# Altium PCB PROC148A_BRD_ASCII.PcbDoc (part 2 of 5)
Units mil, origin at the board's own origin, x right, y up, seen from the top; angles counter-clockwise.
Board outline 7150 x 3764 mil, 4 copper layers (Top Layer, GND01, PWR/GND02, Bottom Layer), stack 60.96 mil thick; 312 components, 352 nets, 2206 pads, 423 vias.
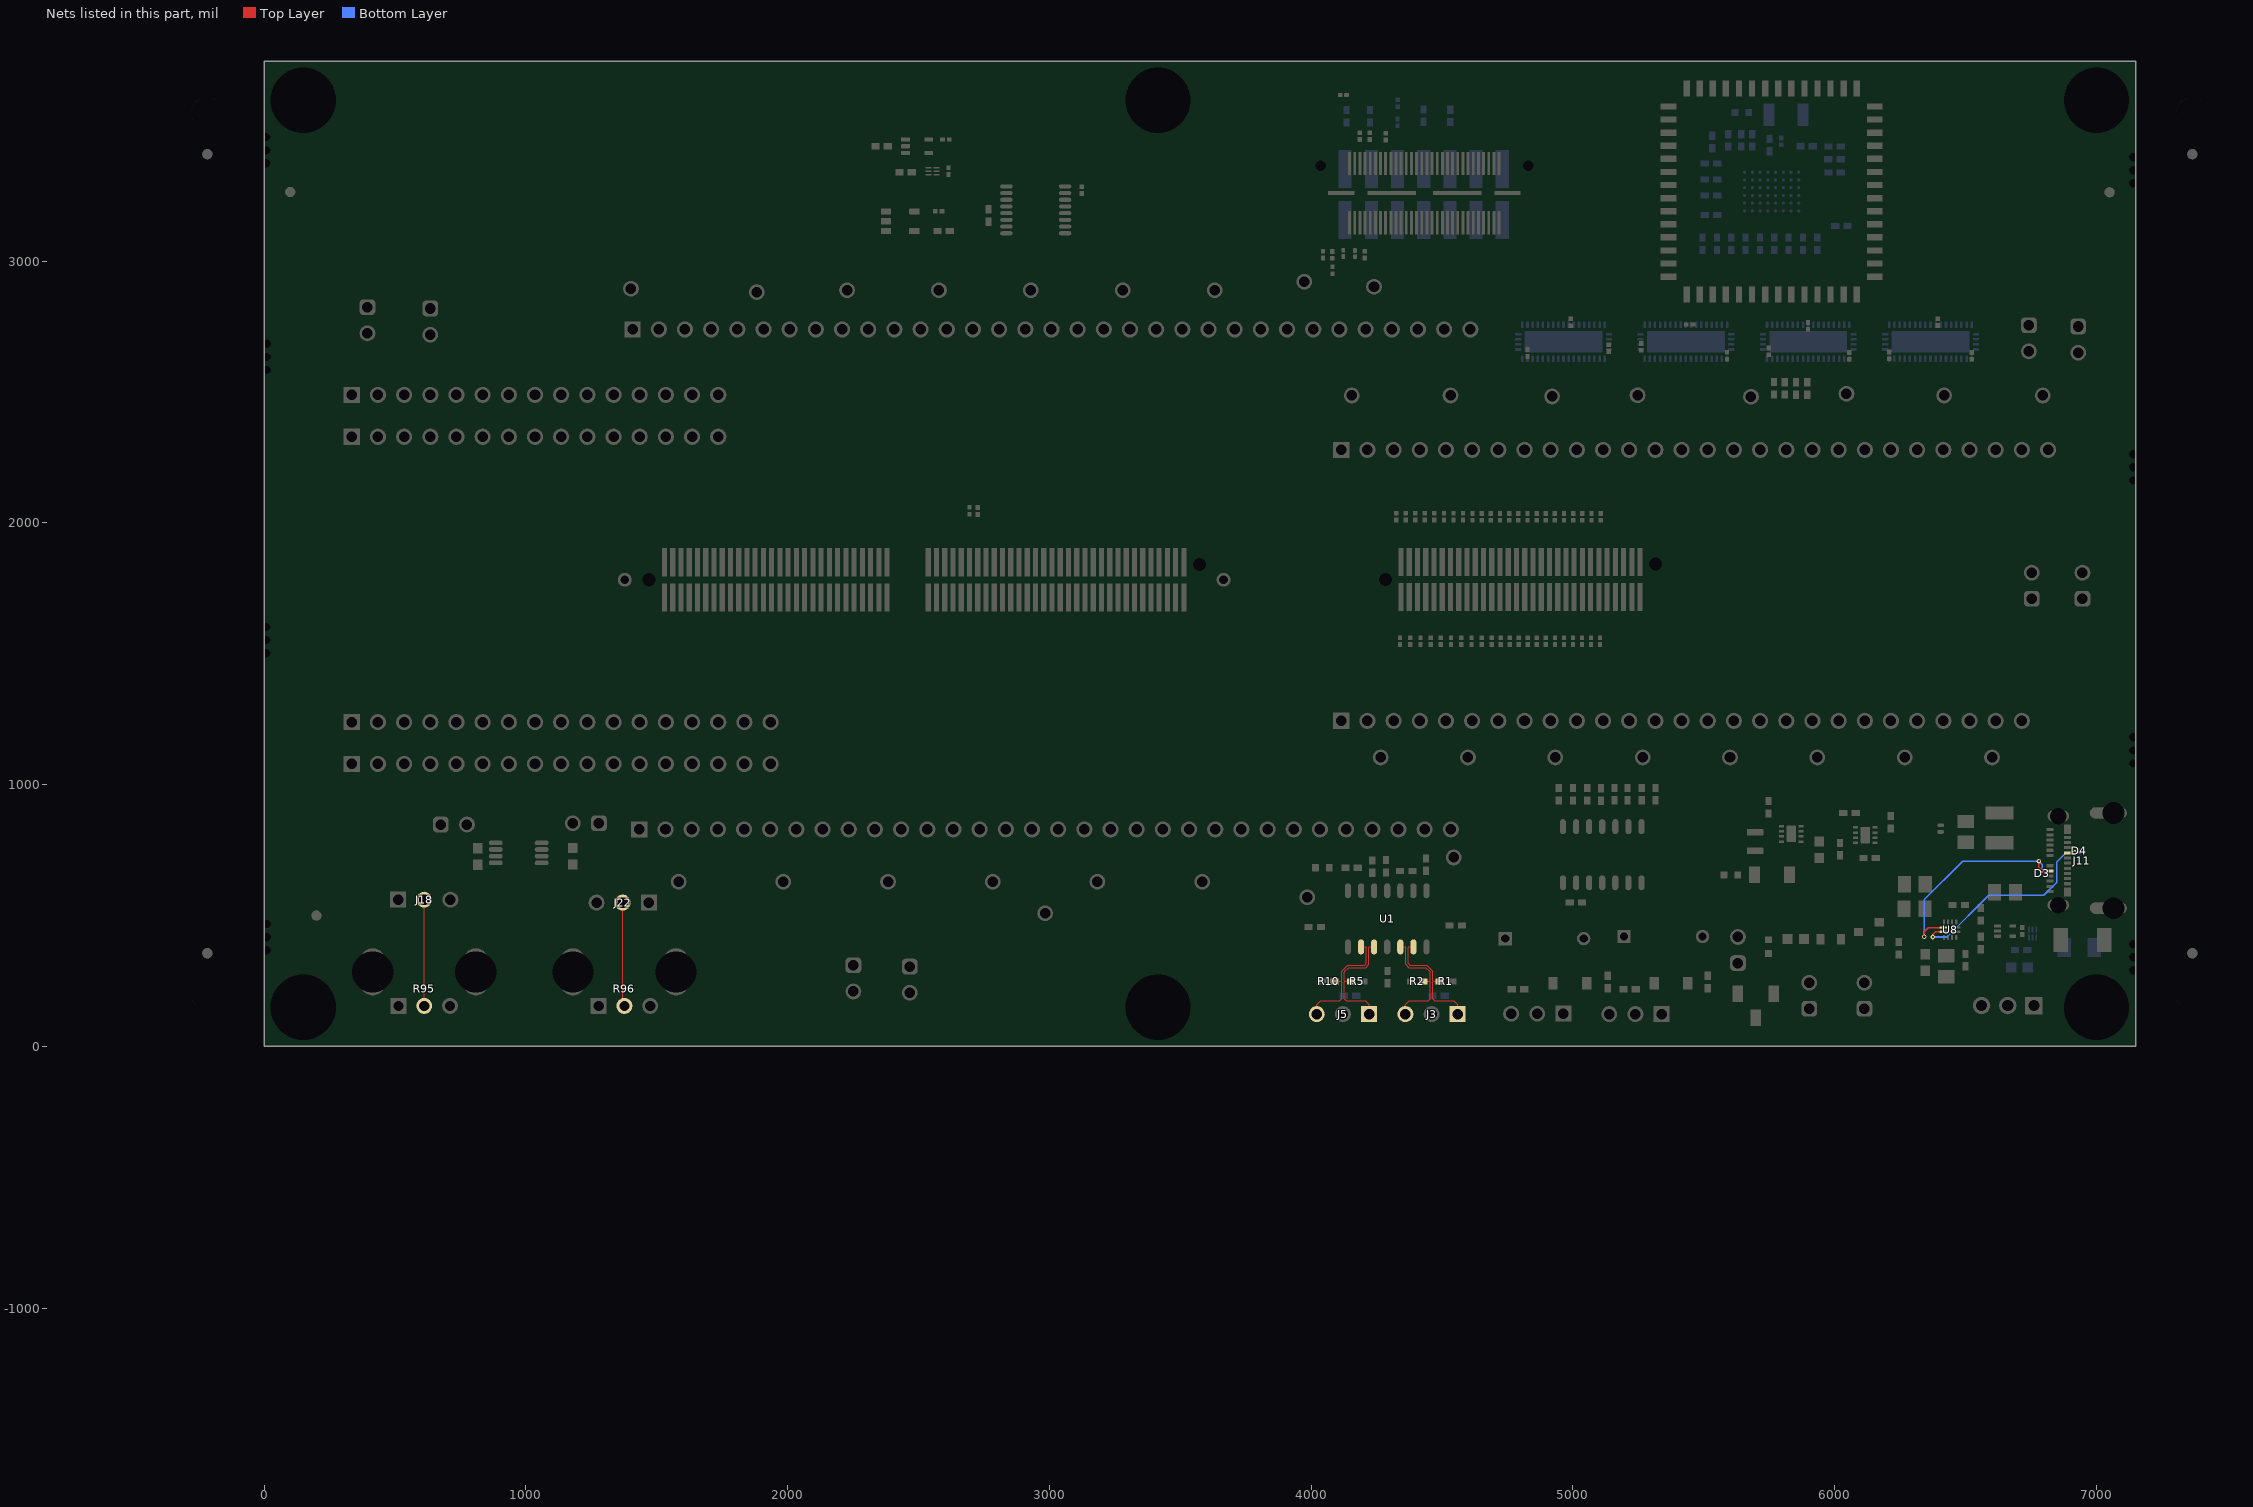
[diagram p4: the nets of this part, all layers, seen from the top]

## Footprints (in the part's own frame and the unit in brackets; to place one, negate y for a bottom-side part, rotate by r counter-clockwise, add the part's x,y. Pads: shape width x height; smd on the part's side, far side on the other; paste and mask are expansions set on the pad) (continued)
FP-2012670005_CONN_USB_9MM39_8MM21-MFG [mm]
  rrect100% 1.1x2.1 hole 1.6 slot 0.6 at 0 deg paste-1000 mask+0: 1(-4.32,3.205) 2(4.32,3.205)
  rrect100% 0.6x2.1 hole 2.1 slot 0.6 at 0 deg paste-1000 mask+0: 3(-4.62,-2.155) 4(4.62,-2.155)
  rrect100% 1.1x3.6 smd paste-1000 mask+0: 3(-4.62,-1.655) 4(4.62,-1.655)
  rrect100% 1.1x3.6 smd far side paste-1000 mask+0: 3(-4.62,-1.655) 4(4.62,-1.655)
  rrect33% 0.3x0.7 smd paste+0 mask+0: A1(-3,4.015) A2(-2.5,4.015) A3(-2,4.015) A4(-1.5,4.015) A5(-1,4.015) A6(-0.5,4.015) A7(0.5,4.015) A8(1,4.015) A9(1.5,4.015) A10(2,4.015) A11(2.5,4.015) A12(3,4.015) B2(2.25,2.315) B3(1.75,2.315) B4(1.25,2.315) B5(0.75,2.315) B6(0.25,2.315) B7(-0.25,2.315) B8(-0.75,2.315) B9(-1.25,2.315) B10(-1.75,2.315) B11(-2.25,2.315)
  rrect14% 0.9x0.7 smd paste+0 mask+0: B1(3.05,2.315) B12(-3.05,2.315)
  silkscreen extent -4.77,0.52 4.77,5.03
FP-A6TN-1104_PTH_SW_7MM50_4MM48-MFG [mm]
  rect 1.3x1.3 hole 0.8 paste-1000 mask+0: 1(0,-3.81)
  round 1.3 hole 0.8 paste-1000 mask+0: 2(0,3.81)
FP-BLM18EG121SN1D_0603-MFG [mm]
  rrect15% 0.65x0.7 smd paste+0 mask+0: 1(-0.675,0) 2(0.675,0)
  silkscreen extent -0.87,-0.8 0.87,0.8
FP-DSG0008A-MFG [mm]
  rrect40% 0.5x0.25 smd paste+0 mask+0: 1(-0.95,0.75) 2(-0.95,0.25) 3(-0.95,-0.25) 4(-0.95,-0.75) 5(0.95,-0.75) 6(0.95,-0.25) 7(0.95,0.25) 8(0.95,0.75)
  rrect11% 0.9x1.6 smd paste-1000 mask+0: 9(0,0)
  silkscreen extent -1.88,-1.39 1,1.4
FP-ERJ-1GNF33R2C_0201-IPC_B [mil]
  rrect28% 17.88x14.28 smd paste+0 mask+0: 1(-11.98,0) 2(11.98,0)
  silkscreen extent -21,-23 21,23
FP-IS67WVE4M16EBLL-70BLA1_TFBGA48-IPC_C [mm]
  round 0.298 smd paste+0 mask+0: A1(-1.875,2.625) A2(-1.125,2.625) A3(-0.375,2.625) A4(0.375,2.625) A5(1.125,2.625) A6(1.875,2.625) B1(-1.875,1.875) B2(-1.125,1.875) B3(-0.375,1.875) B4(0.375,1.875) B5(1.125,1.875) B6(1.875,1.875) C1(-1.875,1.125) C2(-1.125,1.125) C3(-0.375,1.125) C4(0.375,1.125) C5(1.125,1.125) C6(1.875,1.125) D1(-1.875,0.375) D2(-1.125,0.375) D3(-0.375,0.375) D4(0.375,0.375) D5(1.125,0.375) D6(1.875,0.375) E1(-1.875,-0.375) E2(-1.125,-0.375) E3(-0.375,-0.375) E4(0.375,-0.375) E5(1.125,-0.375) E6(1.875,-0.375) F1(-1.875,-1.125) F2(-1.125,-1.125) F3(-0.375,-1.125) F4(0.375,-1.125) F5(1.125,-1.125) F6(1.875,-1.125) G1(-1.875,-1.875) G2(-1.125,-1.875) G3(-0.375,-1.875) G4(0.375,-1.875) G5(1.125,-1.875) G6(1.875,-1.875) H1(-1.875,-2.625) H2(-1.125,-2.625) H3(-0.375,-2.625) H4(0.375,-2.625) H5(1.125,-2.625) H6(1.875,-2.625)
  silkscreen extent -3.62,-4 3,4
FP-PTV09A-8025U-B103_PTH_POT_27MM4_9MM7-MFG [mm]
  rrect6% 1.55x1.55 hole 1 paste-1000 mask+0: 1(-2.5,8)
  round 1.55 hole 1 paste-1000 mask+0: 2(0,8) 3(2.5,8)
  rrect100% 2.4x4.6 hole 4 slot 1.8 at 0 deg paste-1000 mask+0: 4(-5,11.3) 5(5,11.3)
  silkscreen extent -5.62,4.5 4.85,13.95
FP-TSW-115-23-T-S-MFG [mm]
  rect 1.57x1.57 hole 1.02 paste-1000 mask+0: 1(-17.78,0)
  round 1.57 hole 1.02 paste-1000 mask+0: 2(-15.24,0) 3(-12.7,0) 4(-10.16,0) 5(-7.62,0) 6(-5.08,0) 7(-2.54,0) 8(0,0) 9(2.54,0) 10(5.08,0) 11(7.62,0) 12(10.16,0) 13(12.7,0) 14(15.24,0) 15(17.78,0)
  silkscreen extent -19.24,-1.95 19.24,1.34
FP-TSW-117-23-T-S-MFG [mm]
  rect 1.57x1.57 hole 1.02 paste-1000 mask+0: 1(-20.32,0)
  round 1.57 hole 1.02 paste-1000 mask+0: 2(-17.78,0) 3(-15.24,0) 4(-12.7,0) 5(-10.16,0) 6(-7.62,0) 7(-5.08,0) 8(-2.54,0) 9(0,0) 10(2.54,0) 11(5.08,0) 12(7.62,0) 13(10.16,0) 14(12.7,0) 15(15.24,0) 16(17.78,0) 17(20.32,0)
  silkscreen extent -21.78,-1.95 21.78,1.34
FP-TSW-127-23-T-S-MFG [mm]
  rect 1.57x1.57 hole 1.02 paste-1000 mask+0: 1(-33.02,0)
  round 1.57 hole 1.02 paste-1000 mask+0: 2(-30.48,0) 3(-27.94,0) 4(-25.4,0) 5(-22.86,0) 6(-20.32,0) 7(-17.78,0) 8(-15.24,0) 9(-12.7,0) 10(-10.16,0) 11(-7.62,0) 12(-5.08,0) 13(-2.54,0) 14(0,0) 15(2.54,0) 16(5.08,0) 17(7.62,0) 18(10.16,0) 19(12.7,0) 20(15.24,0) 21(17.78,0) 22(20.32,0) 23(22.86,0) 24(25.4,0) 25(27.94,0) 26(30.48,0) 27(33.02,0)
  silkscreen extent -35.14,-1.34 34.48,1.34
FP-TSW-128-23-T-S-0 [mm]
  rect 1.57x1.57 hole 1.02 paste-1000 mask+0: 1(-34.29,0)
  round 1.57 hole 1.02 paste-1000 mask+0: 2(-31.75,0) 3(-29.21,0) 4(-26.67,0) 5(-24.13,0) 6(-21.59,0) 7(-19.05,0) 8(-16.51,0) 9(-13.97,0) 10(-11.43,0) 11(-8.89,0) 12(-6.35,0) 13(-3.81,0) 14(-1.27,0) 15(1.27,0) 16(3.81,0) 17(6.35,0) 18(8.89,0) 19(11.43,0) 20(13.97,0) 21(16.51,0) 22(19.05,0) 23(21.59,0) 24(24.13,0) 25(26.67,0) 26(29.21,0) 27(31.75,0) 28(34.29,0)
  silkscreen extent -35.75,-1.95 35.75,1.34
FP-TSW-132-23-T-S-MFG [mm]
  rect 1.57x1.57 hole 1.02 paste-1000 mask+0: 1(-39.37,0)
  round 1.57 hole 1.02 paste-1000 mask+0: 2(-36.83,0) 3(-34.29,0) 4(-31.75,0) 5(-29.21,0) 6(-26.67,0) 7(-24.13,0) 8(-21.59,0) 9(-19.05,0) 10(-16.51,0) 11(-13.97,0) 12(-11.43,0) 13(-8.89,0) 14(-6.35,0) 15(-3.81,0) 16(-1.27,0) 17(1.27,0) 18(3.81,0) 19(6.35,0) 20(8.89,0) 21(11.43,0) 22(13.97,0) 23(16.51,0) 24(19.05,0) 25(21.59,0) 26(24.13,0) 27(26.67,0) 28(29.21,0) 29(31.75,0) 30(34.29,0) 31(36.83,0) 32(39.37,0)
  silkscreen extent -41.55,-1.34 40.83,1.34
FP-TSW-133-23-T-S-MFG [mm]
  rect 1.57x1.57 hole 1.02 paste-1000 mask+0: 1(-40.64,0)
  round 1.57 hole 1.02 paste-1000 mask+0: 2(-38.1,0) 3(-35.56,0) 4(-33.02,0) 5(-30.48,0) 6(-27.94,0) 7(-25.4,0) 8(-22.86,0) 9(-20.32,0) 10(-17.78,0) 11(-15.24,0) 12(-12.7,0) 13(-10.16,0) 14(-7.62,0) 15(-5.08,0) 16(-2.54,0) 17(0,0) 18(2.54,0) 19(5.08,0) 20(7.62,0) 21(10.16,0) 22(12.7,0) 23(15.24,0) 24(17.78,0) 25(20.32,0) 26(22.86,0) 27(25.4,0) 28(27.94,0) 29(30.48,0) 30(33.02,0) 31(35.56,0) 32(38.1,0) 33(40.64,0)
  silkscreen extent -42.1,-1.95 42.1,1.34
LP-M67K_Green [mm] "Osram"
  rect 0.8x1 smd: 1(-1,0) 2(1,0)
  silkscreen extent -0.3,-0.75 1.78,0.75
MHNP_M3_PANHEAD_PHILLIPS#1 [mil]
  round 121 hole 126 unplated mask+0: ""(0,0)
  Keep-Out Layer circle w1: c0,0 r126
MHNP_M3_PANHEAD_PHILLIPS#2 [mil]
  round 245 hole 250 unplated mask+0: ""(0,0)
  Keep-Out Layer circle w1: c0,0 r126
Molex_0022284033 [mm] "Header, 2.54mm, 3x1, TH"
  rect 1.55x1.55 hole 1.02: 1(-2.54,0)
  round 1.55 hole 1.02: 2(0,0) 3(2.54,0)
  silkscreen extent -3.81,-1.24 3.81,1.5
MSPL_GPMC_MOD [mil]
  rect 61x24 smd mask+0: 1(-393.7,325) 2(-393.7,275) 3(-393.7,225) 4(-393.7,175) 5(-393.7,125) 6(-393.7,75) 7(-393.7,25) 8(-393.7,-25) 9(-393.7,-75) 10(-393.7,-125) 11(-393.7,-175) 12(-393.7,-225) 13(-393.7,-275) 14(-393.7,-325) 29(393.7,-325) 30(393.7,-275) 31(393.7,-225) 32(393.7,-175) 33(393.7,-125) 34(393.7,-75) 35(393.7,-25) 36(393.7,25) 37(393.7,75) 38(393.7,125) 39(393.7,175) 40(393.7,225) 41(393.7,275) 42(393.7,325)
  rect 24x61 smd mask+0: 15(-325,-393.7) 16(-275,-393.7) 17(-225,-393.7) 18(-175,-393.7) 19(-125,-393.7) 20(-75,-393.7) 21(-25,-393.7) 22(25,-393.7) 23(75,-393.7) 24(125,-393.7) 25(175,-393.7) 26(225,-393.7) 27(275,-393.7) 28(325,-393.7) 43(325,393.7) 44(275,393.7) 45(225,393.7) 46(175,393.7) 47(125,393.7) 48(75,393.7) 49(25,393.7) 50(-25,393.7) 51(-75,393.7) 52(-125,393.7) 53(-175,393.7) 54(-225,393.7) 55(-275,393.7) 56(-325,393.7)
  silkscreen extent -450,-405 405,405
ONSC-SOT-23-3-318-08_V [mm] "SOT23, 3-Leads, Body 2.92x1.3mm, Pitch 0.95mm"
  rect 0.9x0.8 smd: 1(-1,0.95) 2(-1,-0.95) 3(1,0)
  silkscreen extent -1.13,-1.46 0.65,2.02
PW0016A_L [mm] "TSOP, 16-Leads, Body 5x4.4mm, Pitch 0.65mm, IPC High Density"
  oval 1.2x0.4 smd: 1(-2.85,2.275) 2(-2.85,1.625) 3(-2.85,0.975) 4(-2.85,0.325) 5(-2.85,-0.325) 6(-2.85,-0.975) 7(-2.85,-1.625) 8(-2.85,-2.275) 9(2.85,-2.275) 10(2.85,-1.625) 11(2.85,-0.975) 12(2.85,-0.325) 13(2.85,0.325) 14(2.85,0.975) 15(2.85,1.625) 16(2.85,2.275)
  silkscreen extent -2,-2.55 1.85,2.55
RUA0042A-MFG [mm]
  rrect40% 0.6x0.25 smd paste+0 mask+0: 1(-1.65,4) 2(-1.65,3.5) 3(-1.65,3) 4(-1.65,2.5) 5(-1.65,2) 6(-1.65,1.5) 7(-1.65,1) 8(-1.65,0.5) 9(-1.65,0) 10(-1.65,-0.5) 11(-1.65,-1) 12(-1.65,-1.5) 13(-1.65,-2) 14(-1.65,-2.5) 15(-1.65,-3) 16(-1.65,-3.5) 17(-1.65,-4) 22(1.65,-4) 23(1.65,-3.5) 24(1.65,-3) 25(1.65,-2.5) 26(1.65,-2) 27(1.65,-1.5) 28(1.65,-1) 29(1.65,-0.5) 30(1.65,0) 31(1.65,0.5) 32(1.65,1) 33(1.65,1.5) 34(1.65,2) 35(1.65,2.5) 36(1.65,3) 37(1.65,3.5) 38(1.65,4)
  rrect40% 0.25x0.6 smd paste+0 mask+0: 18(-0.75,-4.4) 19(-0.25,-4.4) 20(0.25,-4.4) 21(0.75,-4.4) 39(0.75,4.4) 40(0.25,4.4) 41(-0.25,4.4) 42(-0.75,4.4)
  rrect5% 2.05x7.55 smd paste-1000 mask+0: 43(0,0)
  silkscreen extent -2.65,-4.55 1.8,4.55
RWB0012A [mm] "QFN, 12-Leads, Body 1.6x1.6mm, Pitch 0.4mm"
  rrect57% 0.7x0.2 smd paste-0.1: 1(-0.65,0.2) 2(-0.65,-0.2) 7(0.65,-0.2) 8(0.65,0.2)
  rrect57% 0.2x0.5 smd: 3(-0.6,-0.75) 4(-0.2,-0.75) 5(0.2,-0.75) 6(0.6,-0.75) 9(0.6,0.75) 10(0.2,0.75) 11(-0.2,0.75) 12(-0.6,0.75)
  silkscreen extent -0.92,-0.91 0.92,0.91
Samtec_QSH-030-01-X-D-A [mm] "Receptacle, 0.5 mm, 30x2, TH"
  rect 2.27x0.279 smd: 1(-2.865,7.25) 2(2.865,7.25) 3(-2.865,6.75) 4(2.865,6.75) 5(-2.865,6.25) 6(2.865,6.25) 7(-2.865,5.75) 8(2.865,5.75) 9(-2.865,5.25) 10(2.865,5.25) 11(-2.865,4.75) 12(2.865,4.75) 13(-2.865,4.25) 14(2.865,4.25) 15(-2.865,3.75) 16(2.865,3.75) 17(-2.865,3.25) 18(2.865,3.25) 19(-2.865,2.75) 20(2.865,2.75) 21(-2.865,2.25) 22(2.865,2.25) 23(-2.865,1.75) 24(2.865,1.75) 25(-2.865,1.25) 26(2.865,1.25) 27(-2.865,0.75) 28(2.865,0.75) 29(-2.865,0.25) 30(2.865,0.25) 31(-2.865,-0.25) 32(2.865,-0.25) 33(-2.865,-0.75) 34(2.865,-0.75) 35(-2.865,-1.25) 36(2.865,-1.25) 37(-2.865,-1.75) 38(2.865,-1.75) 39(-2.865,-2.25) 40(2.865,-2.25) 41(-2.865,-2.75) 42(2.865,-2.75) 43(-2.865,-3.25) 44(2.865,-3.25) 45(-2.865,-3.75) 46(2.865,-3.75) 47(-2.865,-4.25) 48(2.865,-4.25) 49(-2.865,-4.75) 50(2.865,-4.75) 51(-2.865,-5.25) 52(2.865,-5.25) 53(-2.865,-5.75) 54(2.865,-5.75) 55(-2.865,-6.25) 56(2.865,-6.25) 57(-2.865,-6.75) 58(2.865,-6.75) 59(-2.865,-7.25) 60(2.865,-7.25)
  round 0 hole 1.02 unplated: MH1(2.67,10.065) MH2(2.67,-10.065)
  rect 0.43x2.54 smd: MP1(0,8.065) MP4(0,-8.065)
  rect 0.43x4.7 smd: MP2(0,3.175) MP3(0,-3.175)
  silkscreen extent -3.9,-10.66 3.62,10.66
Samtec_TSM-107-01-x-DV [mm] "Header, 2.54mm, 7x2, SMT"
  rect 3.68x1.27 smd: 1(-2.475,7.62) 2(2.475,7.62) 3(-2.475,5.08) 4(2.475,5.08) 5(-2.475,2.54) 6(2.475,2.54) 7(-2.475,0) 8(2.475,0) 9(-2.475,-2.54) 10(2.475,-2.54) 11(-2.475,-5.08) 12(2.475,-5.08) 13(-2.475,-7.62) 14(2.475,-7.62)
  silkscreen extent -1.65,-8.89 1.65,9.03
Samtec_TSW-101-08-x-S [mm] "Header, 2.54mm, 1x1, TH"
  round 1.53 hole 1.02: 1(0,0)
Samtec_TSW-102-08-x-S [mm] "Header, 2.54mm, 2x1, TH"
  rrect50% 1.53x1.53 hole 1.02: 1(-1.27,0)
  round 1.53 hole 1.02: 2(1.27,0)
  silkscreen extent -2.67,-1.27 2.54,1.7
SOD-123 [mm] "On Semi recommended land pattern"
  rect 0.915x1.22 smd: 1(-1.637,0) 2(1.637,0)
  silkscreen extent -2.74,-1.17 2.03,1.17
SW_CAS-120TA [mm] "COPAL ELECTRONICS"
  rect 1.6x1 smd: 1(-1.15,1.75) 2(1.15,0) 3(-1.15,-1.75)
  silkscreen extent -2,-2.85 1.4,2.92
TFM201610ALMA [mm] "TDK"
  rrect17% 0.6x1.6 smd: 1(-0.9,0) 2(0.9,0)
TI_Stacked_Overlay_Small [mil]
WEEE_Minimum [mil] "WEEElie bin"
  silkscreen extent 22,-71 54,74
Wurth_60900213421 [mil] "Shunt, 2.54mm, Black"
  round 1 on Mech3: 0(0,0)

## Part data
C1 C2 C5: library part CMP-0006675-2, "CAP, CERM, 0.1 uF, 50 V, +/- 20%, X7R, 0402"
C3 C4: library part CMP-0006712-2, "CAP, CERM, 4700 pF, 100 V, +/- 10%, X7R, 0402"
C6 C7: library part CMP-0084239-1, "CAP, CERM, 220 pF, 50 V,+/- 10%, X8R, AEC-Q200 Grade 0, 0402"
C8 C26 C27 C29: library part CMP-0007727-2, "CAP, CERM, 0.1 uF, 50 V, +/- 20%, X7R, 0805"
C9 C11 C12 C13 C14 C15 C16 C17 C18 C19 C20 C21 C22 C23 C24 C25 C37 C38 C39 C40 C43: library part CMP-0009717-2, "CAP, CERM, 0.1 uF, 16 V, +/- 10%, X5R, 0201"
C10: library part CMP-0081135-1, "CAP, CERM, 10 µF, 50 V,+/- 10%, X7R, 1210"
C28: library part CMP-0079201-1, "CAP, CERM, 10 µF, 50 V,+/- 10%, X7R, 1210"
C30 C41: library part CMP-0007206-4, "CAP, CERM, 300 pF, 50 V, +/- 5%, C0G/NP0, 0603"
C31: library part CMP-0006412-2, "CAP, CERM, 1000 pF, 50 V, +/- 5%, C0G/NP0, 0402"
C32: library part CMP-0008959-2, "CAP, CERM, 22 uF, 10 V, +/- 10%, X7R, 1206"
C33: library part CMP-0007501-5, "CAP, CERM, 10 uF, 25 V, +/- 20%, X5R, 0603"
C34: library part CMP-0009436-2, "CAP, CERM, 1000 pF, 2000 V, +/- 10%, X7R, 1808"
C35 C36: library part CMP-0006608-2, "CAP, CERM, 1 uF, 25 V, +/- 10%, X5R, 0402"
C44: library part CMP-0007174-4, "CAP, CERM, 0.01 uF, 50 V, +/- 5%, C0G/NP0, 0603"
D1 D6: library part CMP-0029001-2, "Diode, Ultrafast, 100 V, 0.15 A, SOD-123"
D2: library part CMP-0073591-4, "Automotive 1-Channel Ultra-Low-Capacitance IEC ESD Protection Diode, DPY0002A (X1SON-2)"
D3 D4: library part CMP-0073601-1, "1-Channel ESD Protection Diode for USB Type-C and Thunderbolt 3, DPL0002A (X2SON-2)"
D5: library part CMP-0002879-2, "LED, Green, SMD"
FB3 FB4 FB5 FB6: library part CMP-0089199-1, "120 Ohms @ 100MHz 1  Ferrite Bead 0603 (1608 Metric) 2A 40mOhm"
FID1 FID2 FID3 FID4 FID5 FID6: library part CMP-0077181-1, "Fiducial mark.  There is nothing to buy or mount."
J1: library part CMP-0003859-2, "C2000 controlCARD-180HSEC (60-pin addon) connector, SMT"
J2: library part CMP-0003814-2, "C2000 controlCARD-120HSEC connector, SMT"
J3 J5 J7 J8 J18 J22: library part CMP-0055332-1, "Header, 2.54mm, 3x1, Tin, TH"
J4 J13 J16 J17 J19 J23 J26 J27 J28 J29 J30 J65 J66: library part CMP-0077643-1, "Header, 2.54mm, 2x1, Gold, TH"
J6 J14: library part CMP-02766-001472-1, "CONN HEADER VERT 17POS 2.54MM"
J9: library part CMP-0075524-1, "Receptacle, 0.5 mm, 30x2, Gold, TH"
J10: library part CMP-0075611-2, "Header, 2.54mm, 7x2, Gold, SMT"
J11: library part CMP-0093552-1, "USB-C (USB TYPE-C) USB 3.2 Gen 2 (USB 3.1 Gen 2, Superspeed + (USB 3.1)) Receptacle Connector 24 Position Surface Mount, Right Angle; Through Hole"
J12 J15: library part CMP-02766-001466-1, "CONN HEADER VERT 15POS 2.54MM"
J20: library part CMP-02766-001470-1, "CONN HEADER VERT 32POS 2.54MM"
J21: library part CMP-02766-001386-1, "CONN HEADER VERT 33POS 2.54MM"
J24: library part CMP-02766-001392-1, "CONN HEADER VERT 27POS 2.54MM"
J25: library part CMP-02766-001385-1, "CONN HEADER VERT 28POS 2.54MM"
J31 J32 J33 J34 J35 J36 J37 J38 J39 J40 J41 J42 J43 J44 J45 J46 J47 J48 J49 J50 J51 J52 J53 J54 J55 J56 J57 J58 J59 J60 J61 J62 J63 J64: library part CMP-0079328-1, "Header, 2.54mm, 1x1, Gold, TH"
L1: library part CMP-0081094-1, "Inductor, Shielded, Metal Composite, 2.2 µH, 1.9 A, 0.152 ohm, AEC-Q200 Grade 0, SMD"
Logo1: library part CMP-0074844-1
Logo2: library part CMP-0074838-1, "Texas Instrument Corporate Signature"
Logo3: library part CMP-0074847-1, "FCC_disclaimer"
Logo4: library part CMP-0074769-1
Q1: library part CMP-1058-00767-1, "Power MOSFET, 200 mA, 50 V, N-Channel, 3-Pin SOT-23, Pb-Free, Tape and Reel"
R1 R2 R5 R10: library part CMP-0026462-2, "RES, 59.0, 1%, 0.063 W, AEC-Q200 Grade 0, 0402"
R3 R6 R53 R56 R89 R92: library part CMP-0026822-3, "RES, 0, 5%, 0.063 W, AEC-Q200 Grade 0, 0402"
R4 R7 R88 R91: library part CMP-0026908-3, "RES, 33, 5%, 0.063 W, AEC-Q200 Grade 0, 0402"
R8 R9: library part CMP-0026994-4, "RES, 10 k, 5%, 0.1 W, AEC-Q200 Grade 0, 0402"
R11: library part CMP-0026829-3, "RES, 110, 5%, 0.063 W, AEC-Q200 Grade 0, 0402"
R12 R48 R59 R60 R61 R62 R63 R64 R65 R66 R67 R68 R69 R70 R71 R72: library part CMP-0026880-3, "RES, 22, 5%, 0.063 W, AEC-Q200 Grade 0, 0402"
R13 R14 R20 R22 R37 R38 R39 R73 R74 R75 R76 R77 R78 R79 R80 R81 R82 R83 R85 R86 R87 R90 R93: library part CMP-0026825-5, "RES, 10 k, 5%, 0.063 W, AEC-Q200 Grade 0, 0402"
R15 R16 R23: library part CMP-0083836-1, "RES, 100, 1%, 0.05 W, 0201"
R17: library part CMP-0027280-3, "RES, 4.70 k, 1%, 0.05 W, 0201"
R18 R19 R21: library part CMP-0089575-2, "Res Thick Film 0201 33.2 Ohm 1% 0.05W(1/20W) ±200ppm/C Pad SMD Automotive T/R"
R24 R26 R27 R28 R29 R30 R31 R32 R33 R34 R35 R40 R41 R42 R43 R44 R45 R46 R97 R98 R99 R100 R101 R102 R103 R104 R105 R106 R107 R108 R109 R110 R111 R112 R113 R114 R115 R116 R117 R118 R119 R120 R121 R122 R123 R124 R125: library part CMP-0027309-2, "RES, 10.0, 1%, 0.05 W, 0201"
R25: library part CMP-0027008-4, "RES, 0, 5%, 0.05 W, 0201"
R36 R84: library part CMP-0026071-3, "RES, 1.00 k, 1%, 0.063 W, AEC-Q200 Grade 0, 0402"
R47: library part CMP-0027015-3, "RES, 22, 5%, 0.05 W, AEC-Q200 Grade 1, 0201"
R49 R50: library part CMP-0026700-1, "RES, 4.70 k, 1%, 0.1 W, 0402"
R51: library part CMP-0021811-3, "RES, 909 k, 1%, 0.125 W, AEC-Q200 Grade 0, 0805"
R52: library part CMP-0025817-4, "RES, 4.7 k, 5%, 0.1 W, AEC-Q200 Grade 0, 0603"
R54: library part CMP-0026677-1, "RES, 200 k, 1%, 0.1 W, 0402"
R55: library part CMP-0025756-4, "RES, 220, 5%, 0.1 W, AEC-Q200 Grade 0, 0603"
R57: library part CMP-0016716-3, "RES, 1.00 M, 1%, 0.25 W, AEC-Q200 Grade 0, 1206"
R58 R94: library part CMP-0025950-3, "RES, 100 k, 1%, 0.063 W, AEC-Q200 Grade 0, 0402"
R95 R96: library part CMP-0096228-1, "10k Ohm 1 Gang Linear Through Hole, Snap In Potentiometer None 1.0 Kierros Carbon 0.05W, 1/20W PC Pins, Board Locks"
S1: library part CMP-0002139-2, "Switch, Slide, SPDT  100mA, SMT"
SH-J1 SH-J2 SH-J3 SH-J4: library part CMP-0003761-2, "Shunt, 2.54mm, Gold, Black"
SW1 SW2: library part CMP-0086077-1, "Dip Switch SPST 1 Position Through Hole Slide (Standard) Actuator 25mA 24VDC"
SW3: library part CMP-0091791-1, "Toggle Switch SPDT Through Hole  3A 120V"
U1: library part CMP-0074638-2, "Automotive High Speed Dual CAN Transceiver, D0014A (SOIC-14)"
U2: library part CMP-0077655-1, "Automotive Dual LIN Transceiver, D0014A (SOIC-14)"
U3: library part CMP-0095867-1, "Cellular RAM Pseudo SRAM, 4Mx16, 1.7 to 1.95V, 70ns, TFBGA-48"
U4 U5 U6 U7: library part CMP-0093539-2, "IC MUX/DEMUX DDR3 1:2 42WQFN"
U8: library part CMP-0073634-2, "USB Type-C  for USB 2.0 CC Port Controller, RWB0012A (X2QFN-12)"
U9: library part CMP-0051530-2, "Single 2-Input Positive-NOR Gate, DRL0005A, LARGE T&R"
U10: library part CMP-04913-000004-1, "IC PWR SWITCH N-CHAN 1:1 8WSON"
U11: library part CMP-0037798-2, "Buck Step Down Regulator with 3 to 17 V Input and 3.3 V Output, -40 to 85 degC, 8-Pin WSON (DSG), Green (RoHS & no Sb/Br)"
U12: library part CMP-0076540-1, "4-Bit One-of-2 FET Multiplexer/Demultiplexer 2.5-V/3.3-V Low-Voltage, High-Bandwidth Bus Switch, PW0016A (TSSOP-16)"
U13: library part CMP-0051684-3, "Single Inverter, DCK0005A, LARGE T&R"
U14 U18: library part CMP-0051419-5, "Single 2-Input Positive-AND Gate, DSF0006A, LARGE T&R"
U15: library part CMP-0051529-2, "Single 2-Input Positive-NOR Gate, DBV0005A (SOT-23-5)"
U16: library part CMP-0013309-4, "OPA2837DGK, DGK0008A (VSSOP-8)"
ZZ1: library part CMP-0003616-3
ZZ2: library part CMP-0077236-1
ZZ3: library part CMP-0077237-1
ZZ4: library part CMP-0077238-1

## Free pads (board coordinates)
  round 0.01 on Mech5: 1(-691.22,-1531.82) 1(-691.2,-1531.33) 1(-690.94,-1530.69) 1(-690.11,-1530.74) 1(-690.04,-1530.89) 1(-689.31,-1531.4) 1(-689.31,-1530.74) 1(-689.28,-1530.88) 1(-689.02,-1531.25) 1(-688.5,-1529.82) 1(-686.8,-1531.48) 1(-686.39,-1531.17)
  round 0.04 on Mech5: 1(-690.56,-1530.37) 1(-690.56,-1530.27) 1(-690.56,-1530.17) 1(-690.56,-1530.07) 1(-690.56,-1529.97) 1(-690.56,-1529.87) 1(-690.56,-1529.77) 1(-690.46,-1530.37) 1(-690.46,-1530.27) 1(-690.46,-1530.17) 1(-690.46,-1530.07) 1(-690.46,-1529.97) 1(-690.46,-1529.87) 1(-690.46,-1529.77) 1(-690.36,-1530.37) 1(-690.36,-1530.27) 1(-690.36,-1530.17) 1(-690.36,-1530.07) 1(-690.36,-1529.97) 1(-690.36,-1529.87) 1(-690.36,-1529.77) 1(-690.26,-1530.37) 1(-690.26,-1530.27) 1(-690.26,-1530.17) 1(-690.26,-1530.07) 1(-690.26,-1529.97) 1(-690.26,-1529.87) 1(-690.26,-1529.77) 1(-690.16,-1532.37) 1(-690.16,-1532.27) 1(-690.16,-1532.17) 1(-690.16,-1532.07) 1(-690.16,-1531.97) 1(-690.16,-1531.87) 1(-690.16,-1531.77) 1(-690.16,-1530.37) 1(-690.16,-1530.27) 1(-690.16,-1530.17) 1(-690.16,-1530.07) 1(-690.16,-1529.97) 1(-690.16,-1529.87) 1(-690.16,-1529.77) 1(-690.06,-1532.37) 1(-690.06,-1532.27) 1(-690.06,-1532.17) 1(-690.06,-1532.07) 1(-690.06,-1531.97) 1(-690.06,-1531.87) 1(-690.06,-1531.77) 1(-690.06,-1530.37) 1(-690.06,-1530.27) 1(-690.06,-1530.17) 1(-690.06,-1530.07) 1(-690.06,-1529.97) 1(-690.06,-1529.87) 1(-690.06,-1529.77) 1(-689.96,-1532.37) 1(-689.96,-1532.27) 1(-689.96,-1532.17) 1(-689.96,-1532.07) 1(-689.96,-1531.97) 1(-689.96,-1531.87) 1(-689.96,-1531.77) 1(-689.96,-1530.37) 1(-689.96,-1530.27) 1(-689.96,-1530.17) 1(-689.96,-1530.07) 1(-689.96,-1529.97) 1(-689.96,-1529.87) 1(-689.96,-1529.77) 1(-689.86,-1532.37) 1(-689.86,-1532.27) 1(-689.86,-1532.17) 1(-689.86,-1532.07) 1(-689.86,-1531.97) 1(-689.86,-1531.87) 1(-689.86,-1531.77) 1(-689.86,-1530.37) 1(-689.86,-1530.27) 1(-689.86,-1530.17) 1(-689.86,-1530.07) 1(-689.86,-1529.97) 1(-689.86,-1529.87) 1(-689.86,-1529.77) 1(-689.76,-1532.37) 1(-689.76,-1532.27) 1(-689.76,-1532.17) 1(-689.76,-1532.07) 1(-689.76,-1531.97) 1(-689.76,-1531.87) 1(-689.76,-1531.77) 1(-689.76,-1530.37) 1(-689.76,-1530.27) 1(-689.76,-1530.17) 1(-689.76,-1530.07) 1(-689.76,-1529.97) 1(-689.76,-1529.87) 1(-689.76,-1529.77) 1(-689.66,-1532.37) 1(-689.66,-1532.27) 1(-689.66,-1532.17) 1(-689.66,-1532.07) 1(-689.66,-1531.97) 1(-689.66,-1531.87) 1(-689.66,-1531.77) 1(-689.66,-1530.37) 1(-689.66,-1530.27) 1(-689.66,-1530.17) 1(-689.66,-1530.07) 1(-689.66,-1529.97) 1(-689.66,-1529.87) 1(-689.66,-1529.77) 1(-689.56,-1532.37) 1(-689.56,-1532.27) 1(-689.56,-1532.17) 1(-689.56,-1532.07) 1(-689.56,-1531.97) 1(-689.56,-1531.87) 1(-689.56,-1531.77) 1(-689.56,-1530.37) 1(-689.56,-1530.27) 1(-689.56,-1530.17) 1(-689.56,-1530.07) 1(-689.56,-1529.97) 1(-689.56,-1529.87) 1(-689.56,-1529.77) 1(-689.46,-1532.37) 1(-689.46,-1532.27) 1(-689.46,-1532.17) 1(-689.46,-1532.07) 1(-689.46,-1531.97) 1(-689.46,-1531.87) 1(-689.46,-1531.77) 1(-689.46,-1530.37) 1(-689.46,-1530.27) 1(-689.46,-1530.17) 1(-689.46,-1530.07) 1(-689.46,-1529.97) 1(-689.46,-1529.87) 1(-689.46,-1529.77) 1(-689.36,-1532.37) 1(-689.36,-1532.27) 1(-689.36,-1532.17) 1(-689.36,-1532.07) 1(-689.36,-1531.97) 1(-689.36,-1531.87) 1(-689.36,-1531.77) 1(-689.36,-1530.37) 1(-689.36,-1530.27) 1(-689.36,-1530.17) 1(-689.36,-1530.07) 1(-689.36,-1529.97) 1(-689.36,-1529.87) 1(-689.36,-1529.77) 1(-689.26,-1532.37) 1(-689.26,-1532.27) 1(-689.26,-1532.17) 1(-689.26,-1532.07) 1(-689.26,-1531.97) 1(-689.26,-1531.87) 1(-689.26,-1531.77) 1(-689.26,-1530.37) 1(-689.26,-1530.27) 1(-689.26,-1530.17) 1(-689.26,-1530.07) 1(-689.26,-1529.97) 1(-689.26,-1529.87) 1(-689.26,-1529.77) 1(-689.16,-1532.37) 1(-689.16,-1532.27) 1(-689.16,-1532.17) 1(-689.16,-1532.07) 1(-689.16,-1531.97) 1(-689.16,-1531.87) 1(-689.16,-1531.77) 1(-689.16,-1530.37) 1(-689.16,-1530.27) 1(-689.16,-1530.17) 1(-689.16,-1530.07) 1(-689.16,-1529.97) 1(-689.16,-1529.87) 1(-689.16,-1529.77) 1(-689.06,-1532.37) 1(-689.06,-1532.27) 1(-689.06,-1532.17) 1(-689.06,-1532.07) 1(-689.06,-1531.97) 1(-689.06,-1531.87) 1(-689.06,-1531.77) 1(-689.06,-1530.37) 1(-689.06,-1530.27) 1(-689.06,-1530.17) 1(-689.06,-1530.07) 1(-689.06,-1529.97) 1(-689.06,-1529.87) 1(-689.06,-1529.77) 1(-688.96,-1532.37) 1(-688.96,-1532.27) 1(-688.96,-1532.17) 1(-688.96,-1532.07) 1(-688.96,-1531.97) 1(-688.96,-1531.87) 1(-688.96,-1531.77) 1(-688.96,-1530.37) 1(-688.96,-1530.27) 1(-688.96,-1530.17) 1(-688.96,-1530.07) 1(-688.96,-1529.97) 1(-688.96,-1529.87) 1(-688.96,-1529.77) 1(-688.86,-1532.37) 1(-688.86,-1532.27) 1(-688.86,-1532.17) 1(-688.86,-1532.07) 1(-688.86,-1531.97) 1(-688.86,-1531.87) 1(-688.86,-1531.77) 1(-688.86,-1530.37) 1(-688.86,-1530.27) 1(-688.86,-1530.17) 1(-688.86,-1530.07) 1(-688.86,-1529.97) 1(-688.86,-1529.87) 1(-688.86,-1529.77) 1(-688.76,-1532.37) 1(-688.76,-1532.27) 1(-688.76,-1532.17) 1(-688.76,-1532.07) 1(-688.76,-1531.97) 1(-688.76,-1531.87) 1(-688.76,-1531.77) 1(-688.76,-1530.37) 1(-688.76,-1530.27) 1(-688.76,-1530.17) 1(-688.76,-1530.07) 1(-688.76,-1529.97) 1(-688.76,-1529.87) 1(-688.76,-1529.77) 1(-688.66,-1532.37) 1(-688.66,-1532.27) 1(-688.66,-1532.17) 1(-688.66,-1532.07) 1(-688.66,-1531.97) 1(-688.66,-1531.87) 1(-688.66,-1531.77) 1(-688.66,-1530.37) 1(-688.66,-1530.27) 1(-688.66,-1530.17) 1(-688.66,-1530.07) 1(-688.66,-1529.97) 1(-688.66,-1529.87) 1(-688.66,-1529.77) 1(-688.56,-1532.37) 1(-688.56,-1532.27) 1(-688.56,-1532.17) 1(-688.56,-1532.07) 1(-688.56,-1531.97) 1(-688.56,-1531.87) 1(-688.56,-1531.77) 1(-688.56,-1530.37) 1(-688.56,-1530.27) 1(-688.56,-1530.17) 1(-688.56,-1530.07) 1(-688.56,-1529.97) 1(-688.56,-1529.87) 1(-688.56,-1529.77) 1(-688.46,-1532.37) 1(-688.46,-1532.27) 1(-688.46,-1532.17) 1(-688.46,-1532.07) 1(-688.46,-1531.97) 1(-688.46,-1531.87) 1(-688.46,-1531.77) 1(-688.46,-1530.37) 1(-688.46,-1530.27) 1(-688.46,-1530.17) 1(-688.46,-1530.07) 1(-688.46,-1529.97) 1(-688.46,-1529.87) 1(-688.46,-1529.77) 1(-688.36,-1532.37) 1(-688.36,-1532.27) 1(-688.36,-1532.17) 1(-688.36,-1532.07) 1(-688.36,-1531.97) 1(-688.36,-1531.87) 1(-688.36,-1531.77) 1(-688.36,-1530.37) 1(-688.36,-1530.27) 1(-688.36,-1530.17) 1(-688.36,-1530.07) 1(-688.36,-1529.97) 1(-688.26,-1532.37) 1(-688.26,-1532.27) 1(-688.26,-1532.17) 1(-688.26,-1532.07) 1(-688.26,-1531.97) 1(-688.26,-1531.87) 1(-688.26,-1531.77) 1(-688.26,-1530.37) 1(-688.26,-1530.27) 1(-688.26,-1530.17) 1(-688.26,-1530.07) 1(-688.26,-1529.97) 1(-688.16,-1532.37) 1(-688.16,-1532.27) 1(-688.16,-1532.17) 1(-688.16,-1532.07) 1(-688.16,-1531.97) 1(-688.16,-1531.87) 1(-688.16,-1531.77) 1(-688.16,-1530.37) 1(-688.16,-1530.27) 1(-688.16,-1530.17) 1(-688.16,-1530.07) 1(-688.16,-1529.97) 1(-688.06,-1532.37) 1(-688.06,-1532.27) 1(-688.06,-1532.17) 1(-688.06,-1532.07) 1(-688.06,-1531.97) 1(-688.06,-1531.87) 1(-688.06,-1531.77) 1(-688.06,-1530.37) 1(-688.06,-1530.27) 1(-688.06,-1530.17) 1(-688.06,-1530.07) 1(-688.06,-1529.97) 1(-687.96,-1532.37) 1(-687.96,-1532.27) 1(-687.96,-1532.17) 1(-687.96,-1532.07) 1(-687.96,-1531.97) 1(-687.96,-1531.87) 1(-687.96,-1531.77) 1(-687.96,-1530.37) 1(-687.96,-1530.27) 1(-687.96,-1530.17) 1(-687.96,-1530.07) 1(-687.96,-1529.97) 1(-687.86,-1532.37) 1(-687.86,-1532.27) 1(-687.86,-1532.17) 1(-687.86,-1532.07) 1(-687.86,-1531.97) 1(-687.86,-1531.87) 1(-687.86,-1531.77) 1(-687.86,-1530.37) 1(-687.86,-1530.27) 1(-687.86,-1530.17) 1(-687.86,-1530.07) 1(-687.86,-1529.97) 1(-687.86,-1529.87) 1(-687.86,-1529.77) 1(-687.76,-1532.37) 1(-687.76,-1532.27) 1(-687.76,-1532.17) 1(-687.76,-1532.07) 1(-687.76,-1531.97) 1(-687.76,-1531.87) 1(-687.76,-1531.77) 1(-687.76,-1530.37) 1(-687.76,-1530.27) 1(-687.76,-1530.17) 1(-687.76,-1530.07) 1(-687.76,-1529.97) 1(-687.76,-1529.87) 1(-687.76,-1529.77) 1(-687.66,-1532.37) 1(-687.66,-1532.27) 1(-687.66,-1532.17) 1(-687.66,-1532.07) 1(-687.66,-1531.97) 1(-687.66,-1531.87) 1(-687.66,-1531.77) 1(-687.66,-1530.37) 1(-687.66,-1530.27) 1(-687.66,-1530.17) 1(-687.66,-1530.07) 1(-687.66,-1529.97) 1(-687.66,-1529.87) 1(-687.66,-1529.77) 1(-687.56,-1532.37) 1(-687.56,-1532.27) 1(-687.56,-1532.17) 1(-687.56,-1532.07) 1(-687.56,-1531.97) 1(-687.56,-1531.87) 1(-687.56,-1531.77) 1(-687.56,-1530.37) 1(-687.56,-1530.27) 1(-687.56,-1530.17) 1(-687.56,-1530.07) 1(-687.56,-1529.97) 1(-687.56,-1529.87) 1(-687.56,-1529.77) 1(-687.46,-1532.37) 1(-687.46,-1532.27) 1(-687.46,-1532.17) 1(-687.46,-1532.07) 1(-687.46,-1531.97) 1(-687.46,-1531.87) 1(-687.46,-1531.77) 1(-687.46,-1530.37) 1(-687.46,-1530.27) 1(-687.46,-1530.17) 1(-687.46,-1530.07) 1(-687.46,-1529.97) 1(-687.46,-1529.87) 1(-687.46,-1529.77) 1(-687.36,-1532.37) 1(-687.36,-1532.27) 1(-687.36,-1532.17) 1(-687.36,-1532.07) 1(-687.36,-1531.97) 1(-687.36,-1531.87) 1(-687.36,-1531.77) 1(-687.36,-1530.37) 1(-687.36,-1530.27) 1(-687.36,-1530.17) 1(-687.36,-1530.07) 1(-687.36,-1529.97) 1(-687.36,-1529.87) 1(-687.36,-1529.77) 1(-687.16,-1532.37) 1(-687.16,-1532.27) 1(-687.16,-1532.17) 1(-687.16,-1532.07) 1(-687.16,-1531.97) 1(-687.16,-1531.87) 1(-687.16,-1531.77) 1(-687.16,-1530.37) 1(-687.16,-1530.27) 1(-687.16,-1530.17) 1(-687.16,-1530.07) 1(-687.16,-1529.97) 1(-687.16,-1529.87) 1(-687.16,-1529.77) 1(-687.06,-1532.37) 1(-687.06,-1532.27) 1(-687.06,-1532.17) 1(-687.06,-1532.07) 1(-687.06,-1531.97) 1(-687.06,-1531.87) 1(-687.06,-1531.77) 1(-687.06,-1530.37) 1(-687.06,-1530.27) 1(-687.06,-1530.17) 1(-687.06,-1530.07) 1(-687.06,-1529.97) 1(-687.06,-1529.87) 1(-687.06,-1529.77) 1(-686.96,-1532.37) 1(-686.96,-1532.27) 1(-686.96,-1532.17) 1(-686.96,-1532.07) 1(-686.96,-1531.97) 1(-686.96,-1531.87) 1(-686.96,-1531.77) 1(-686.96,-1530.37) 1(-686.96,-1530.27) 1(-686.96,-1530.17) 1(-686.96,-1530.07) 1(-686.96,-1529.97) 1(-686.96,-1529.87) 1(-686.96,-1529.77) 1(-686.86,-1532.37) 1(-686.86,-1532.27) 1(-686.86,-1532.17) 1(-686.86,-1532.07) 1(-686.86,-1531.97) 1(-686.86,-1531.87) 1(-686.86,-1531.77) 1(-686.86,-1530.37) 1(-686.86,-1530.27) 1(-686.86,-1530.17) 1(-686.86,-1530.07) 1(-686.86,-1529.97) 1(-686.86,-1529.87) 1(-686.86,-1529.77) 1(-686.76,-1532.37) 1(-686.76,-1532.27) 1(-686.76,-1532.17) 1(-686.76,-1532.07) 1(-686.76,-1531.97) 1(-686.76,-1531.87) 1(-686.76,-1531.77) 1(-686.76,-1530.37) 1(-686.76,-1530.27) 1(-686.76,-1530.17) 1(-686.76,-1530.07) 1(-686.76,-1529.97) 1(-686.76,-1529.87) 1(-686.76,-1529.77) 1(-686.66,-1532.37) 1(-686.66,-1532.27) 1(-686.66,-1532.17) 1(-686.66,-1532.07) 1(-686.66,-1531.97) 1(-686.66,-1531.87) 1(-686.66,-1531.77) 1(-686.66,-1530.37) 1(-686.66,-1530.27) 1(-686.66,-1530.17) 1(-686.66,-1530.07) 1(-686.66,-1529.97) 1(-686.66,-1529.87) 1(-686.66,-1529.77) 1(-686.56,-1532.37) 1(-686.56,-1532.27) 1(-686.56,-1532.17) 1(-686.56,-1532.07) 1(-686.56,-1531.97) 1(-686.56,-1531.87) 1(-686.56,-1531.77) 1(-686.56,-1530.37) 1(-686.56,-1530.27) 1(-686.56,-1530.17) 1(-686.56,-1530.07) 1(-686.56,-1529.97) 1(-686.56,-1529.87) 1(-686.56,-1529.77) 1(-686.46,-1532.37) 1(-686.46,-1532.27) 1(-686.46,-1532.17) 1(-686.46,-1532.07) 1(-686.46,-1531.97) 1(-686.46,-1531.87) 1(-686.46,-1531.77) 1(-686.46,-1530.37) 1(-686.46,-1530.27) 1(-686.46,-1530.17) 1(-686.46,-1530.07) 1(-686.46,-1529.97) 1(-686.46,-1529.87) 1(-686.46,-1529.77) 1(-686.36,-1532.37) 1(-686.36,-1532.27) 1(-686.36,-1532.17) 1(-686.36,-1532.07) 1(-686.36,-1531.97) 1(-686.36,-1531.87) 1(-686.36,-1531.77) 1(-686.36,-1530.37) 1(-686.36,-1530.27) 1(-686.36,-1530.17) 1(-686.36,-1530.07) 1(-686.36,-1529.97) 1(-686.36,-1529.87) 1(-686.36,-1529.77) 1(-686.26,-1532.37) 1(-686.26,-1532.27) 1(-686.26,-1532.17) 1(-686.26,-1532.07) 1(-686.26,-1531.97) 1(-686.26,-1531.87) 1(-686.26,-1531.77) 1(-686.26,-1530.37) 1(-686.26,-1530.27) 1(-686.26,-1530.17) 1(-686.26,-1530.07) 1(-686.26,-1529.97) 1(-686.26,-1529.87) 1(-686.26,-1529.77) 1(-686.16,-1532.37) 1(-686.16,-1532.27) 1(-686.16,-1532.17) 1(-686.16,-1532.07) 1(-686.16,-1531.97) 1(-686.16,-1531.87) 1(-686.16,-1531.77) 1(-686.16,-1530.37) 1(-686.16,-1530.27) 1(-686.16,-1530.17) 1(-686.16,-1530.07) 1(-686.16,-1529.97) 1(-686.16,-1529.87) 1(-686.16,-1529.77) 1(-686.06,-1532.37) 1(-686.06,-1532.27) 1(-686.06,-1532.17) 1(-686.06,-1532.07) 1(-686.06,-1531.97) 1(-686.06,-1531.87) 1(-686.06,-1531.77) 1(-686.06,-1530.37) 1(-686.06,-1530.27) 1(-686.06,-1530.17) 1(-686.06,-1530.07) 1(-686.06,-1529.97) 1(-686.06,-1529.87) 1(-686.06,-1529.77) 1(-685.96,-1532.37) 1(-685.96,-1532.27) 1(-685.96,-1532.17) 1(-685.96,-1532.07) 1(-685.96,-1531.97) 1(-685.96,-1531.87) 1(-685.96,-1531.77) 1(-685.96,-1530.37) 1(-685.96,-1530.27) 1(-685.96,-1530.17) 1(-685.96,-1530.07) 1(-685.96,-1529.97) 1(-685.96,-1529.87) 1(-685.96,-1529.77) 1(-685.86,-1532.37) 1(-685.86,-1532.27) 1(-685.86,-1532.17) 1(-685.86,-1532.07) 1(-685.86,-1531.97) 1(-685.86,-1531.87) 1(-685.86,-1531.77) 1(-685.86,-1530.37) 1(-685.86,-1530.27) 1(-685.86,-1530.17) 1(-685.86,-1530.07) 1(-685.86,-1529.97) 1(-685.86,-1529.87) 1(-685.86,-1529.77) 1(-685.76,-1532.37) 1(-685.76,-1532.27) 1(-685.76,-1532.17) 1(-685.76,-1532.07) 1(-685.76,-1531.97) 1(-685.76,-1531.87) 1(-685.76,-1531.77) 1(-685.76,-1530.37) 1(-685.76,-1530.27) 1(-685.76,-1530.17) 1(-685.76,-1530.07) 1(-685.76,-1529.97) 1(-685.76,-1529.87) 1(-685.76,-1529.77) 1(-685.66,-1532.37) 1(-685.66,-1532.27) 1(-685.66,-1532.17) 1(-685.66,-1532.07) 1(-685.66,-1531.97) 1(-685.66,-1531.87) 1(-685.66,-1531.77) 1(-685.66,-1530.37) 1(-685.66,-1530.27) 1(-685.66,-1530.17) 1(-685.66,-1530.07) 1(-685.66,-1529.97) 1(-685.66,-1529.87) 1(-685.66,-1529.77) 1(-685.56,-1532.37) 1(-685.56,-1532.27) 1(-685.56,-1532.17) 1(-685.56,-1532.07) 1(-685.56,-1531.97) 1(-685.56,-1531.87) 1(-685.56,-1531.77) 1(-685.56,-1530.37) 1(-685.56,-1530.27) 1(-685.56,-1530.17) 1(-685.56,-1530.07) 1(-685.56,-1529.97) 1(-685.56,-1529.87) 1(-685.56,-1529.77) 1(-685.46,-1532.37) 1(-685.46,-1532.27) 1(-685.46,-1532.17) 1(-685.46,-1532.07) 1(-685.46,-1531.97) 1(-685.46,-1531.87) 1(-685.46,-1531.77) 1(-685.46,-1530.37) 1(-685.46,-1530.27) 1(-685.46,-1530.17) 1(-685.46,-1530.07) 1(-685.46,-1529.97) 1(-685.46,-1529.87) 1(-685.46,-1529.77) 1(-685.36,-1532.37) 1(-685.36,-1532.27) 1(-685.36,-1532.17) 1(-685.36,-1532.07) 1(-685.36,-1531.97) 1(-685.36,-1531.87) 1(-685.36,-1531.77) 1(-685.36,-1530.37) 1(-685.36,-1530.27) 1(-685.36,-1530.17) 1(-685.36,-1530.07) 1(-685.36,-1529.97) 1(-685.36,-1529.87) 1(-685.36,-1529.77) 1(-685.26,-1532.37) 1(-685.26,-1532.27) 1(-685.26,-1532.17) 1(-685.26,-1532.07) 1(-685.26,-1531.97) 1(-685.26,-1531.87) 1(-685.26,-1531.77) 1(-685.26,-1530.37) 1(-685.26,-1530.27) 1(-685.26,-1530.17) 1(-685.26,-1530.07) 1(-685.26,-1529.97) 1(-685.26,-1529.87) 1(-685.26,-1529.77) 1(-685.16,-1532.37) 1(-685.16,-1532.27) 1(-685.16,-1532.17) 1(-685.16,-1532.07) 1(-685.16,-1531.97) 1(-685.16,-1531.87) 1(-685.16,-1531.77) 1(-685.16,-1530.37) 1(-685.16,-1530.27) 1(-685.16,-1530.17) 1(-685.16,-1530.07) 1(-685.16,-1529.97) 1(-685.16,-1529.87) 1(-685.16,-1529.77) 1(-685.06,-1532.37) 1(-685.06,-1532.27) 1(-685.06,-1532.17) 1(-685.06,-1532.07) 1(-685.06,-1531.97) 1(-685.06,-1531.87) 1(-685.06,-1531.77) 1(-685.06,-1530.37) 1(-685.06,-1530.27) 1(-685.06,-1530.17) 1(-685.06,-1530.07) 1(-685.06,-1529.97) 1(-685.06,-1529.87) 1(-685.06,-1529.77) 1(-684.96,-1532.37) 1(-684.96,-1532.27) 1(-684.96,-1532.17) 1(-684.96,-1532.07) 1(-684.96,-1531.97) 1(-684.96,-1531.87) 1(-684.96,-1531.77) 1(-684.96,-1530.37) 1(-684.96,-1530.27) 1(-684.96,-1530.17) 1(-684.96,-1530.07) 1(-684.96,-1529.97) 1(-684.96,-1529.87) 1(-684.96,-1529.77) 1(-684.86,-1532.37) 1(-684.86,-1532.27) 1(-684.86,-1532.17) 1(-684.86,-1532.07) 1(-684.86,-1531.97) 1(-684.86,-1531.87) 1(-684.86,-1531.77) 1(-684.86,-1530.37) 1(-684.86,-1530.27) 1(-684.86,-1530.17) 1(-684.86,-1530.07) 1(-684.86,-1529.97) 1(-684.86,-1529.87) 1(-684.86,-1529.77) 1(-684.76,-1532.37) 1(-684.76,-1532.27) 1(-684.76,-1532.17) 1(-684.76,-1532.07) 1(-684.76,-1531.97) 1(-684.76,-1531.87) 1(-684.76,-1531.77) 1(-684.76,-1530.37) 1(-684.76,-1530.27) 1(-684.76,-1530.17) 1(-684.76,-1530.07) 1(-684.76,-1529.97) 1(-684.76,-1529.87) 1(-684.76,-1529.77) 1(-684.66,-1532.37) 1(-684.66,-1532.27) 1(-684.66,-1532.17) 1(-684.66,-1532.07) 1(-684.66,-1531.97) 1(-684.66,-1531.87) 1(-684.66,-1531.77) 1(-684.66,-1530.37) 1(-684.66,-1530.27) 1(-684.66,-1530.17) 1(-684.66,-1530.07) 1(-684.66,-1529.97) 1(-684.66,-1529.87) 1(-684.66,-1529.77) 1(-684.56,-1532.37) 1(-684.56,-1532.27) 1(-684.56,-1532.17) 1(-684.56,-1532.07) 1(-684.56,-1531.97) 1(-684.56,-1531.87) 1(-684.56,-1531.77) 1(-684.56,-1530.37) 1(-684.56,-1530.27) 1(-684.56,-1530.17) 1(-684.56,-1530.07) 1(-684.56,-1529.97) 1(-684.56,-1529.87) 1(-684.56,-1529.77) 1(-684.46,-1532.37) 1(-684.46,-1532.27) 1(-684.46,-1532.17) 1(-684.46,-1532.07) 1(-684.46,-1531.97) 1(-684.46,-1531.87) 1(-684.46,-1531.77) 1(-684.46,-1530.37) 1(-684.46,-1530.27) 1(-684.46,-1530.17) 1(-684.46,-1530.07) 1(-684.46,-1529.97) 1(-684.46,-1529.87) 1(-684.46,-1529.77)

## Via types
v1: diameter 18, hole 8, Top Layer to Bottom Layer, tented both sides, 422 vias
v2: diameter 18, hole 8, Top Layer to Bottom Layer, 1 vias

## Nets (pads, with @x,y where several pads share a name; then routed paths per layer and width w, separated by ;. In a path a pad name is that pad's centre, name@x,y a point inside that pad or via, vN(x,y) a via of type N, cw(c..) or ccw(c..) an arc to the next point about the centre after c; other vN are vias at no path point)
ADC_POT1_OUT: J18.2 R95.2 | length 405.7
  Top Layer w4: R95.2@611.85,154.79 J18.2@611.85,560.53
ADC_POT2_OUT: J22.2 R96.2 | length 397.2
  Top Layer w4: J22.2@1370,549.3 1370,161.37 R96.2@1376.57,154.79
C_A5_CC1: D3.2 J11.A5 U8.1 | length 854.5
  Top Layer w6: v1(6341.97,419) 6341.97,437.97 6357.81,453.81 U8.1@6415,453.81 ; v1(6780,707.76) 6780,685 6793.15,671.85 6820.71,671.85 J11.A5@6821.93,670.63
  Bottom Layer w6: v1(6341.97,419) 6341.97,554.61 6341.34,555.24 6341.34,560.22 6488.88,707.76 v1(6780,707.76) 6792.77,694.99 D3.2@6792.77,668.95
C_B5_CC2: D4.2 J11.B5 U8.2 | length 822.6
  Top Layer w6: v1(6375,418) 6374.99,427.99 6385.06,438.06 U8.2@6415,438.06 ; J11.B5@6888.86,739.53 6890.02,740.69 v1(6916.98,740.69)
  Bottom Layer w6: v1(6375,418) 6428.93,418 6588.02,577.09 6798.8,577.09 6848.24,626.53 6848.24,704.71 6884.22,740.69 v1(6916.98,740.69) 6917.48,740.19 6934.65,740.19 D4.2@6935,739.84
CAN0_N: J3.3 R2.1 U1.12 | length 461.4
  Top Layer w4: U1.12@4340.64,379.98 4358.8,379.98 4361.14,377.64 4361.14,313.44 4373.28,301.3 4437.68,301.3 4450.75,288.24 4455.71,283.27 4455.71,251.11 4453.06,248.46 ; J3.3@4359.94,123.67 4359.94,160.07 4374.77,174.9 4447.96,174.9 4455.4,182.34 4455.4,246.12 4453.06,248.46 ; R2.1@4428.53,248.46 4453.06,248.46
CAN0_P: J3.1 R1.2 U1.13 | length 460.9
  Top Layer w4: U1.13@4390.64,379.98 4372.48,379.98 4370.14,377.64 4370.14,317.17 4377.01,310.3 4441.41,310.3 4464.71,287 4464.71,251.09 4467.04,248.76 ; R1.2@4491.28,248.46 4466.75,248.46 4464.4,246.12 4464.4,182.34 4471.85,174.9 4545.04,174.9 4559.87,160.07 J3.1@4559.94,123.67
CAN2_N: J5.3 R10.1 U1.9 | length 460.9
  Top Layer w4: J5.3@4021.41,123.67 4021.41,160.07 4036.25,174.9 4109.43,174.9 4116.88,182.34 4116.88,246.12 4114.53,248.46 R10.1@4090,248.46 ; 4114.24,248.76 4116.57,251.09 4116.57,287 4139.87,310.3 4204.27,310.3 4211.14,317.17 4211.14,377.64 4208.8,379.98 U1.9@4190.64,379.98
CAN2_P: J5.1 R5.2 U1.10 | length 461.4
  Top Layer w4: R5.2@4152.76,248.46 4128.22,248.46 ; J5.1@4221.34,123.67 4221.34,160.07 4206.51,174.9 4133.32,174.9 4125.88,182.34 4125.88,246.12 4128.22,248.46 ; U1.10@4240.64,379.98 4222.48,379.98 4220.14,377.64 4220.14,313.44 4208,301.3 4143.6,301.3 4130.54,288.24 4125.57,283.27 4125.57,251.11 4128.22,248.46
